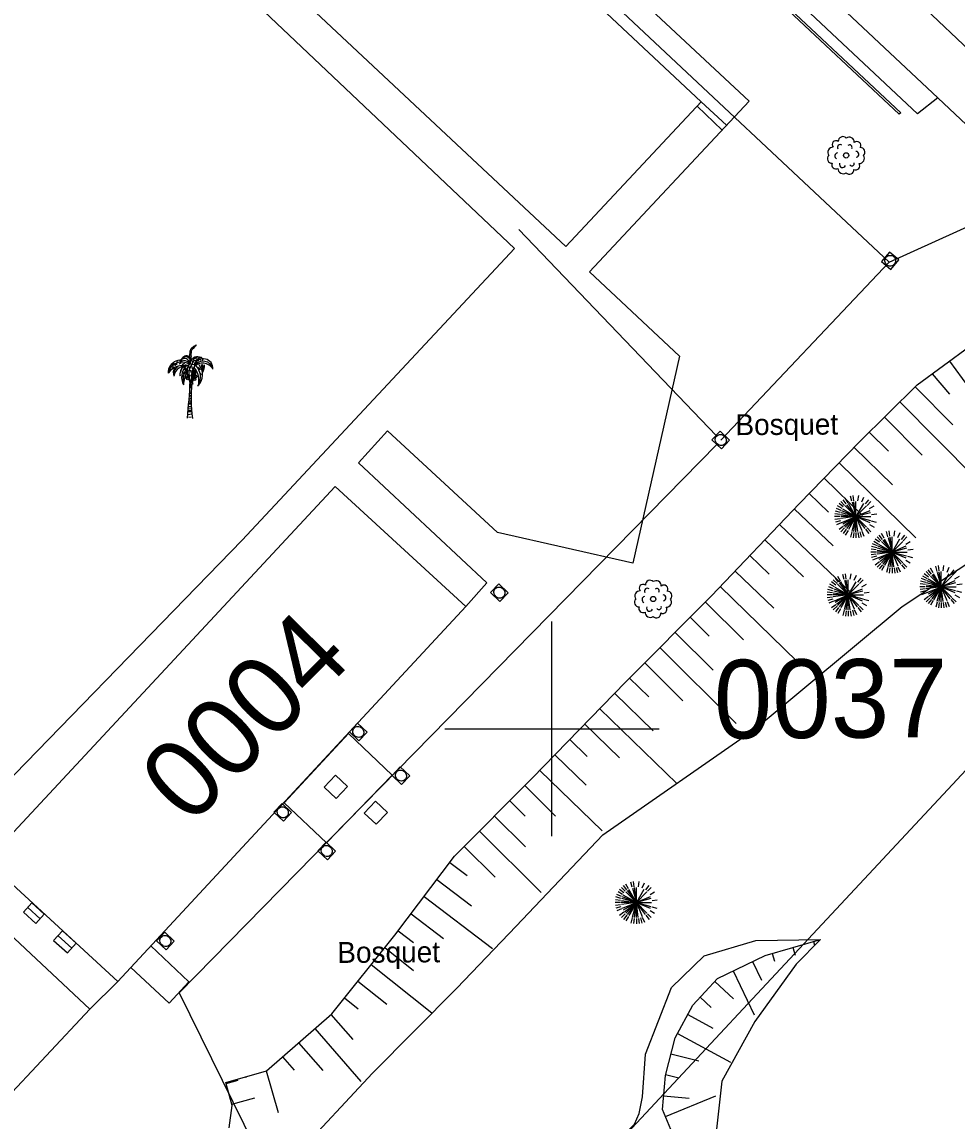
# Model space of a CAD drawing. Extents: x 343997 to 344255, y 298512 to 298767.
# Drawn here: x 344175.3 to 344218.9, y 298581.7 to 298632.9 of the extents above; entities that cross this region are included whole.
import ezdxf

# ---------------------------------------------------------------- set-up
doc = ezdxf.new("R2010")
doc.units = 0
for name, color, linetype in [('Default', 7, 'Continuous'), ('DH_CADRE -CARTOUCHE', 7, 'Continuous'), ('DH_CADRE-CARTOUCHE', 7, 'Continuous'), ('DH_CADRE-CARTOUCHE-NORD', 7, 'Continuous'), ('DH_TEXTE', 7, 'Continuous'), ('DIR-Projet VRD1', 7, 'Continuous'), ('GO_DALLE', 7, 'Continuous'), ('GO_ESCALIER', 7, 'Continuous'), ('GO_MUR', 7, 'Continuous'), ('PC_REBAR', 7, 'Continuous'), ('PS_HATCH', 7, 'Continuous'), ('PS_OBJECT', 7, 'Continuous'), ('PS_PLATE', 7, 'Continuous'), ('RES_EAU PLUVIALE', 7, 'Continuous')]:
    doc.layers.add(name, color=color, linetype=linetype)

# ---------------------------------------------------------------- blocks, each defined once
blk = doc.blocks.new('REG_INC')
at = {"layer": 'Default'}
for p, q in [((0, 0.1), (0.1, 0.1)), ((0, 0), (0, 0.1)), ((0.1, 0.1), (0.1, 0)), ((0.1, 0), (0, 0))]:
    blk.add_line(p, q, dxfattribs=at)
for centre, start, end in [((0.05, 0.0498), 90.00577, 135.00577), ((0.05, 0.05), 45.00687, 90.00687), ((0.0498, 0.05), 135.00554, 180.00554), ((0.0501, 0.05), 180.00663, 225.00663), ((0.0499, 0.0498), 225.00686, 270.00686), ((0.0499, 0.05), 270.00577, 315.00577), ((0.0499, 0.0499), 0.00663, 45.00663), ((0.0501, 0.0499), 315.00554, 0.00554)]:
    blk.add_arc(centre, 0.044, start, end, dxfattribs=at)
blk = doc.blocks.new('R3')
at = {"layer": 'Default'}
for p, q in [((0, 0.1), (0.1, 0.1)), ((0, 0), (0, 0.1)), ((0.1, 0.1), (0.1, 0)), ((0.1, 0), (0, 0))]:
    blk.add_line(p, q, dxfattribs=at)
blk = doc.blocks.new('COCO')
at = {"layer": 'Default'}
for p, q in [((-0.0037, 0.106), (0.0056, 0.1071)), ((0.0058, 0.114), (-0.003, 0.1162)), ((-0.0026, 0.1226), (0.0061, 0.1212)), ((-0.0062, 0.0537), (0.0046, 0.0552)), ((0.0047, 0.0655), (-0.0058, 0.0642)), ((-0.0046, 0.0891), (0.0052, 0.0927)), ((0.0054, 0.0998), (-0.0041, 0.0985)), ((0.0046, 0.0033), (-0.0076, 0.0051)), ((-0.0073, 0.017), (0.0045, 0.0209)), ((0.0045, 0.0292), (-0.007, 0.0288)), ((-0.0068, 0.0371), (0.0045, 0.0374)), ((0.0045, 0.047), (-0.0065, 0.0453))]:
    blk.add_line(p, q, dxfattribs=at)
for points in [[(0.0029, 0.2551), (-0.0016, 0.2896), (0.0002, 0.3125), (0.0059, 0.3241), (0.0173, 0.3348), (0.0189, 0.3356), (0.0282, 0.3415), (0.0266, 0.3373), (0.02, 0.3318), (0.0143, 0.3247), (0.0093, 0.32), (0.0081, 0.3165), (0.0057, 0.3133), (0.0057, 0.3099), (0.006, 0.3037), (0.0039, 0.2989), (0.0039, 0.2944), (0.0049, 0.2877), (0.0037, 0.2841), (0.0013, 0.2736)], [(-0.0636, 0.2639), (-0.0541, 0.2608)], [(-0.0421, 0.258), (-0.0503, 0.2523)], [(-0.0487, 0.268), (-0.0386, 0.265)], [(0.0013, 0.2736), (0.0036, 0.2813), (0.0046, 0.2746)], [(0.0133, 0.2608), (0.0185, 0.2634)], [(0.0196, 0.2687), (0.0323, 0.2715)], [(0.0283, 0.2765), (0.0331, 0.2786)], [(-0.0746, 0.2559), (-0.0864, 0.2483)], [(-0.077, 0.2413), (-0.0836, 0.2333)], [(-0.0607, 0.2534), (-0.0704, 0.2443)], [(-0.0183, 0.2493), (-0.0348, 0.2417), (-0.0401, 0.2307), (-0.0448, 0.2203), (-0.0471, 0.2086), (-0.0474, 0.2023), (-0.0466, 0.1973), (-0.0455, 0.2054), (-0.0451, 0.2146), (-0.0387, 0.2292), (-0.0351, 0.2354), (-0.0284, 0.2404), (-0.0233, 0.2445), (-0.0012, 0.2495)], [(-0.0256, 0.2553), (-0.0385, 0.2508)], [(-0.0276, 0.2151), (-0.0329, 0.2086)], [(-0.0203, 0.2314), (-0.0274, 0.2258)], [(-0.023, 0.2152), (-0.0237, 0.2043)], [(-0.0161, 0.2218), (-0.0158, 0.2122)], [(-0.004, 0.2247), (-0.0081, 0.2179)], [(0.0015, 0.2414), (-0.0056, 0.2352)], [(0.0022, 0.224), (0.0043, 0.213)], [(0.0081, 0.2404), (0.0106, 0.2299)], [(0.0385, 0.237), (0.0469, 0.2254)], [(0.0473, 0.2115), (0.0509, 0.2012)], [(-0.0321, 0.1997), (-0.0364, 0.19)], [(-0.0059, 0.2024), (-0.0083, 0.1998)], [(-0.0025, 0.2032), (0.0002, 0.1954)], [(-0.0055, 0.0716), (0.0048, 0.0717), (0.0049, 0.0787), (-0.0051, 0.0795)]]:
    blk.add_lwpolyline(points, dxfattribs=at)
for centre, radius in [((-0.0187, 0.1897), 0.00384), ((-0.0144, 0.1978), 0.00616), ((-0.0124, 0.1896), 0.00376), ((-0.011, 0.184), 0.00471), ((0.0134, 0.1862), 0.00549), ((0.0208, 0.1822), 0.00626), ((0.0254, 0.1938), 0.00628)]:
    blk.add_circle(centre, radius, dxfattribs=at)
for centre, radius, start, end in [((-0.0427, 0.2113), 0.0595, 43.6121, 181.4625), ((-0.038, 0.1964), 0.0648, 57.9192, 166.6201), ((-0.0123, 0.259), 0.0323, 122.3475, 158.7636), ((-0.0199, 0.2618), 0.0238, 4.5218, 154.101), ((-0.0252, 0.2556), 0.0231, 4.2441, 134.2103), ((-0.016, 0.2647), 0.0255, 21.0861, 122.3475), ((0.0376, 0.2508), 0.0372, 113.7681, 175.3309), ((0.0376, 0.2508), 0.0372, 113.7681, 175.3309), ((0.0418, 0.2527), 0.0326, 97.1248, 183.9512), ((0.1025, 0.2053), 0.0958, 126.6858, 153.1664), ((0.059, 0.2015), 0.0548, 29.5654, 139.3517), ((0.0618, 0.2316), 0.0451, 356.1627, 159.0009), ((0.0609, 0.2187), 0.0468, 12.1077, 148.3146), ((0.0344, 0.2407), 0.0451, 69.0817, 104.862), ((-0.0157, 0.2027), 0.074, 51.2475, 54.5217), ((-0.1005, 0.1577), 0.1786, 37.5668, 40.5156), ((-0.0254, 0.228), 0.0869, 28.4725, 37.0965), ((0.0493, 0.2767), 0.00679, 35.3205, 126.6858), ((-0.0054, 0.2379), 0.0738, 25.8194, 35.3205), ((-0.0291, 0.1543), 0.0918, 76.7389, 142.8025), ((-0.03, 0.212), 0.0482, 151.1331, 199.5942), ((-0.0196, 0.1874), 0.0565, 78.514, 171.3504), ((-0.032, 0.2055), 0.0433, 119.0834, 188.7621), ((0.0362, 0.1922), 0.0754, 136.7113, 208.8221), ((0.0551, 0.179), 0.0879, 137.733, 194.3716), ((0.0649, 0.1599), 0.0949, 145.5146, 182.4528), ((0.062, 0.2159), 0.0753, 153.0868, 230.1124), ((0.0659, 0.2068), 0.0718, 142.3554, 222.2794), ((-0.0007, 0.2465), 0.00563, 81.7475, 144.3035), ((-0.0189, 0.121), 0.1324, 71.3715, 81.7475), ((0.0294, 0.2595), 0.0256, 198.6765, 199.7627), ((0.0963, 0.1939), 0.09, 143.9866, 203.4288), ((0.0544, 0.1816), 0.0474, 137.1953, 172.8987), ((0.0308, 0.2014), 0.0226, 121.4297, 182.29), ((2.7302, 0.0106), 2.7266, 175.4791, 176.5597), ((0.0311, 0.2152), 0.0219, 141.856, 191.5175), ((0.0242, 0.1964), 0.0147, 110.9727, 165.9756), ((0.0404, 0.1878), 0.0354, 125.0585, 146.3893), ((0.0398, 0.2098), 0.0301, 136.4569, 162.0685), ((0.0357, 0.2084), 0.0244, 133.1184, 172.7534), ((-0.0759, 0.1958), 0.0922, 344.8505, 15.8988), ((-0.0404, 0.2045), 0.0619, 329.4666, 26.6793), ((-0.0289, 0.211), 0.0564, 317.8279, 12.3386), ((-0.0543, 0.1744), 0.096, 344.8781, 41.1461), ((-0.0341, 0.19), 0.0828, 46.9767, 50.1231), ((-0.0341, 0.19), 0.0828, 334.0687, 41.194), ((-0.0157, 0.2027), 0.074, 315.1472, 39.0239), ((-0.1704, 0.1849), 0.2327, 7.5978, 16.3666), ((-0.0254, 0.228), 0.0869, 350.8883, 14.7063), ((-0.0482, 0.2552), 0.1161, 339.3597, 356.5925), ((-8.5428, 0.7294), 8.5622, 355.11326, 356.26352), ((-0.0279, 0.1637), 0.0281, 2.1499, 36.6325), ((-0.0265, 0.1505), 0.0316, 339.9997, 25.7228), ((0.0199, 0.166), 0.0176, 166.9443, 185.5966), ((0.0372, 0.1847), 0.0277, 133.5956, 173.487), ((0.0808, 0.1542), 0.0777, 142.2358, 156.28)]:
    blk.add_arc(centre, radius, start, end, dxfattribs=at)
blk.add_ellipse((2.7425, 0.0272), major_axis=(-2.7371, 0.0966), ratio=0.529859, start_param=6.255729, end_param=6.369141, dxfattribs=at)
blk = doc.blocks.new('ARB1')
at = {"layer": 'Default'}
blk.add_circle((0, 0), 0.0122, dxfattribs=at)
for centre, radius, start, end in [((-0.0471, 0.0503), 0.0183, 53.9554, 222.2066), ((-0.0153, 0.0664), 0.0211, 43.6925, 183.5969), ((0.0139, 0.0613), 0.0241, 358.4583, 125.1928), ((0.0501, 0.0468), 0.0183, 325.1444, 131.0175), ((-0.0613, 0.0139), 0.0241, 88.4583, 215.1928), ((-0.0373, -0.0024), 0.0149, 103.7092, 242.3465), ((-0.0276, 0.037), 0.0134, 52.4396, 209.5496), ((0.0164, 0.038), 0.0112, 330.5895, 133.7127), ((0.0458, 0.0052), 0.0137, 276.6214, 88.967), ((0.0613, -0.0139), 0.0241, 268.4583, 35.1928), ((0.0664, 0.0153), 0.0211, 313.6925, 93.5969), ((-0.0664, -0.0153), 0.0211, 133.6925, 273.5969), ((-0.0478, -0.0443), 0.019, 155.2243, 300.9377), ((-0.0163, -0.042), 0.0148, 159.5371, 338.1663), ((0.0271, -0.038), 0.0112, 210.5895, 13.7127), ((0.0448, -0.0483), 0.0188, 243.1323, 33.0297), ((-0.0139, -0.0613), 0.0241, 178.4583, 305.1928), ((0.0153, -0.0664), 0.0211, 223.6925, 3.5969)]:
    blk.add_arc(centre, radius, start, end, dxfattribs=at)
blk = doc.blocks.new('ARB2')
at = {"layer": 'Default'}
for p, q in [((-0.0575, 0.0453), (-0.0775, 0.0605)), ((-0.0513, 0.0525), (-0.0688, 0.0702)), ((-0.0438, 0.0589), (-0.0588, 0.0786)), ((-0.0356, 0.0642), (-0.0481, 0.0858)), ((-0.0181, 0.0716), (-0.0244, 0.0956)), ((-0.0088, 0.0736), (-0.0119, 0.0983)), ((0.0106, 0.0736), (0.0144, 0.0983)), ((0.0287, 0.0684), (0.0388, 0.0914)), ((0.0456, 0.0589), (0.0612, 0.0786)), ((0.0531, 0.0525), (0.0706, 0.0702)), ((-0.0731, 0), (-0.0981, 0)), ((-0.0725, 0.01), (-0.0969, 0.0133)), ((-0.0706, 0.0195), (-0.0944, 0.0259)), ((-0.0675, 0.0286), (-0.09, 0.0381)), ((-0.0631, 0.0373), (-0.0844, 0.0497)), ((0.065, 0.0373), (0.0862, 0.0497)), ((0.0744, 0.01), (0.0987, 0.0133)), ((-0.0725, -0.01), (-0.0969, -0.0133)), ((-0.0706, -0.0195), (-0.0944, -0.0259)), ((-0.0675, -0.0287), (-0.09, -0.0383)), ((-0.0575, -0.0455), (-0.0775, -0.0605)), ((0.065, -0.0373), (0.0862, -0.0498)), ((0.0725, -0.0195), (0.0963, -0.0259)), ((-0.0513, -0.0527), (-0.0688, -0.0702)), ((-0.0438, -0.0591), (-0.0588, -0.0787)), ((-0.0356, -0.0644), (-0.0481, -0.0859)), ((-0.0181, -0.0717), (-0.0244, -0.0956)), ((-0.0088, -0.0737), (-0.0119, -0.0983)), ((0.0013, -0.0741), (0.0013, -0.0989)), ((0.0106, -0.0737), (0.0144, -0.0983)), ((0.02, -0.0717), (0.0263, -0.0956)), ((0.0287, -0.0686), (0.0388, -0.0916)), ((0.0456, -0.0591), (0.0612, -0.0787)), ((0.0531, -0.0527), (0.0706, -0.0702))]:
    blk.add_line(p, q, dxfattribs=at)
for points in [[(-0.0688, 0.0091), (0.0013, 0), (-0.0338, 0.0608)], [(-0.0419, 0.0556), (0.0013, 0), (-0.0638, 0.0269)], [(-0.0169, 0.0677), (0.0013, 0), (-0.06, 0.035)], [(0.0013, 0.0008), (0.0013, 0), (-0.0081, 0.0695)], [(0.0362, 0.0608), (0.0013, 0), (0.0013, 0.0702)], [(-0.0487, -0.0497), (0.0013, 0), (-0.0694, 0)], [(-0.0638, -0.0269), (0.0013, 0), (-0.0688, -0.0092)], [(-0.0487, 0.0495), (0.0013, 0), (-0.0669, 0.0181)], [(-0.0169, -0.0678), (0.0013, 0), (-0.06, -0.0352)], [(-0.0544, -0.0428), (0.0013, 0), (-0.0338, -0.0608)], [(-0.0081, -0.0695), (0.0013, 0), (-0.0419, -0.0558)], [(0.0013, -0.0702), (0.0013, 0), (0, 0)], [(0.0656, 0.0269), (0.0013, 0), (0.0506, 0.0495)], [(0.0688, 0.0181), (0.0013, 0), (0.0713, 0)], [(0.0438, -0.0558), (0.0013, 0), (0.0656, -0.0269)], [(0.0506, -0.0497), (0.0013, 0), (0.0688, -0.0181)], [(0.01, -0.0695), (0.0013, 0), (0.0281, -0.0648)], [(0.0019, 0), (0.0013, 0), (0.0013, -0.0009)]]:
    blk.add_lwpolyline(points, dxfattribs=at)

msp = doc.modelspace()

# ---------------------------------------------------------------- linework, layer by layer
at = {"layer": 'DH_CADRE -CARTOUCHE'}
for p, q in [((344200, 298595), (344200, 298605)), ((344195, 298600), (344205, 298600))]:
    msp.add_line(p, q, dxfattribs=at)
msp.add_lwpolyline([(343997.309, 298660.673), (344147.183, 298520.807), (344245.09, 298625.72), (344095.215, 298765.586)], close=True, dxfattribs=at)
at = {"layer": 'DH_CADRE-CARTOUCHE'}
msp.add_lwpolyline([(344173.884, 298668.877), (344175.641, 298668.318), (344176.928, 298667.79), (344178.107, 298666.872), (344194.798, 298651.17), (344217.989, 298629.411), (344240.944, 298607.781), (344244.256, 298604.654)], dxfattribs=at)
at = {"layer": 'DH_CADRE-CARTOUCHE-NORD'}
for p, q in [((344193.828, 298642.286), (344215.714, 298621.751)), ((344215.714, 298621.751), (344222.758, 298624.96)), ((344198.454, 298623.276), (344207.649, 298613.67)), ((344215.714, 298621.751), (344207.87, 298613.462)), ((344207.679, 298613.259), (344182.63, 298587.693)), ((344182.63, 298587.693), (344198.438, 298555.558))]:
    msp.add_line(p, q, dxfattribs=at)
at = {"layer": 'DIR-Projet VRD1'}
msp.add_line((344180.02, 298669.219), (344245.896, 298606.412), dxfattribs=at)
at = {"layer": 'GO_DALLE'}
for points in [[(344173.637, 298593.851), (344172.292, 298595.161), (344185.567, 298608.8), (344198.259, 298622.397), (344163.217, 298655.561), (344163.898, 298656.291), (344171.693, 298664.218), (344209.192, 298629.258), (344201.744, 298621.299), (344205.95, 298617.379), (344203.771, 298607.721), (344197.46, 298609.156), (344192.341, 298613.899), (344190.988, 298612.393), (344196.963, 298606.8), (344195.985, 298605.701)], [(344208.14, 298628.134), (344206.962, 298629.231), (344206.772, 298629.027), (344207.928, 298627.907)], [(344173.444, 298593.641), (344172.427, 298592.568), (344178.462, 298586.939), (344174.396, 298582.587), (344168.376, 298588.228), (344167.085, 298586.853), (344168.386, 298585.586), (344159.324, 298576.069), (344121.411, 298611.054), (344130.716, 298620.945), (344149.461, 298603.379), (344147.717, 298601.519)], [(344179.76, 298588.225), (344178.462, 298586.939), (344172.427, 298592.568), (344173.444, 298593.641), (344173.637, 298593.851)], [(344181.304, 298589.888), (344183.07, 298588.205), (344182.156, 298587.216), (344180.365, 298588.877)]]:
    msp.add_lwpolyline(points, dxfattribs=at)
msp.add_lwpolyline([(344187.514, 298596.559), (344189.49, 298594.691), (344192.553, 298597.847), (344190.509, 298599.787)], close=True, dxfattribs=at)
at = {"layer": 'GO_ESCALIER'}
for points in [[(344175.763, 298591.898), (344175.363, 298591.462), (344175.943, 298590.936), (344176.339, 298591.368)], [(344177.19, 298590.587), (344176.772, 298590.132), (344177.42, 298589.564), (344177.824, 298590.004)]]:
    msp.add_lwpolyline(points, close=True, dxfattribs=at)
for points in [[(344176.141, 298591.152), (344175.563, 298591.68)], [(344177.622, 298589.784), (344176.981, 298590.359)]]:
    msp.add_lwpolyline(points, dxfattribs=at)
at = {"layer": 'GO_MUR'}
for points in [[(344162.931, 298666.015), (344158.413, 298661.325), (344158.342, 298661.39), (344163.216, 298666.766), (344163.731, 298667.308), (344164.688, 298668.072), (344165.676, 298668.545), (344166.447, 298668.825), (344167.222, 298669.059), (344168.509, 298669.289), (344169.751, 298669.392), (344170.251, 298669.414), (344170.803, 298669.375), (344172.06, 298669.227), (344173.884, 298668.877), (344175.641, 298668.318), (344176.928, 298667.79), (344178.107, 298666.872), (344194.798, 298651.17), (344217.989, 298629.411), (344217.037, 298628.671)], [(344217.037, 298628.671), (344194.049, 298650.256), (344176.274, 298666.89)], [(344175.978, 298666.428), (344193.686, 298649.877), (344216.254, 298628.72), (344216.185, 298628.648), (344193.618, 298649.804), (344175.917, 298666.349)]]:
    msp.add_lwpolyline(points, dxfattribs=at)
at = {"layer": 'PS_HATCH'}
msp.add_lwpolyline([(344182.365, 298573.436), (344182.886, 298573.416), (344183.782, 298573.006), (344188.242, 298571.307), (344188.925, 298571.234), (344191.696, 298571.482), (344193.065, 298571.873), (344193.915, 298572.359), (344194.821, 298573.435), (344196.721, 298576.256), (344197.328, 298576.829), (344198.067, 298577.284), (344202.461, 298580.187), (344203.841, 298581.577), (344204.07, 298582.072), (344204.22, 298582.851), (344204.366, 298584.836), (344205.57, 298587.951), (344207.101, 298589.427), (344209.508, 298590.137), (344212.523, 298590.19)], dxfattribs=at)
at = {"layer": 'PS_OBJECT'}
for p, q in [((344218.523, 298617.14), (344220.003, 298615.124)), ((344217.717, 298616.549), (344218.529, 298615.598)), ((344216.924, 298615.941), (344218.685, 298614.164)), ((344216.214, 298615.237), (344219.734, 298611.684)), ((344215.503, 298614.533), (344217.263, 298612.756)), ((344214.793, 298613.828), (344215.68, 298612.948)), ((344214.086, 298613.12), (344215.876, 298611.374)), ((344213.388, 298612.404), (344216.967, 298608.912)), ((344212.689, 298611.689), (344214.479, 298609.942)), ((344211.99, 298610.973), (344212.891, 298610.105)), ((344211.295, 298610.254), (344213.106, 298608.53)), ((344210.605, 298609.53), (344214.228, 298606.081)), ((344209.915, 298608.805), (344211.727, 298607.081)), ((344209.226, 298608.081), (344210.131, 298607.218)), ((344208.536, 298607.356), (344210.347, 298605.632)), ((344207.846, 298606.631), (344211.43, 298603.143)), ((344207.15, 298605.913), (344208.923, 298604.149)), ((344206.445, 298605.204), (344207.331, 298604.322)), ((344205.739, 298604.495), (344207.512, 298602.731)), ((344205.034, 298603.786), (344208.579, 298600.258)), ((344204.328, 298603.077), (344206.1, 298601.313)), ((344203.622, 298602.368), (344204.514, 298601.492)), ((344202.923, 298601.653), (344204.716, 298599.91)), ((344202.226, 298600.936), (344205.813, 298597.45)), ((344201.529, 298600.218), (344203.143, 298598.65)), ((344200.832, 298599.501), (344201.639, 298598.717)), ((344200.135, 298598.784), (344201.587, 298597.372)), ((344199.438, 298598.066), (344202.343, 298595.243)), ((344198.736, 298597.353), (344200.172, 298595.925)), ((344198.031, 298596.644), (344198.749, 298595.93)), ((344197.325, 298595.935), (344198.761, 298594.506)), ((344196.62, 298595.225), (344199.492, 298592.369)), ((344195.915, 298594.516), (344197.351, 298593.088)), ((344195.246, 298593.775), (344196.053, 298593.163)), ((344194.641, 298592.978), (344196.255, 298591.754)), ((344194.036, 298592.182), (344197.23, 298589.758)), ((344193.432, 298591.385), (344194.948, 298590.234)), ((344192.827, 298590.588), (344193.547, 298590.042)), ((344192.207, 298589.803), (344193.547, 298588.73)), ((344211.229, 298589.814), (344211.333, 298589.455)), ((344212.189, 298590.093), (344212.239, 298589.92)), ((344209.347, 298589.153), (344209.766, 298588.282)), ((344210.268, 298589.535), (344210.372, 298589.178)), ((344191.581, 298589.023), (344194.408, 298586.757)), ((344208.446, 298588.719), (344209.43, 298586.677)), ((344190.956, 298588.242), (344192.298, 298587.166)), ((344207.586, 298588.229), (344208.468, 298587.421)), ((344190.33, 298587.462), (344190.967, 298586.951)), ((344206.911, 298587.491), (344207.428, 298587.017)), ((344189.698, 298586.687), (344190.718, 298585.518)), ((344206.332, 298586.684), (344207.5, 298586.046)), ((344188.945, 298586.029), (344191.098, 298583.562)), ((344205.852, 298585.806), (344208.318, 298584.459)), ((344188.191, 298585.372), (344189.327, 298584.07)), ((344187.437, 298584.714), (344187.977, 298584.096)), ((344205.548, 298584.859), (344206.84, 298584.527)), ((344186.682, 298584.06), (344187.246, 298582.115)), ((344184.813, 298583.473), (344185.367, 298583.624)), ((344185.721, 298583.781), (344185.731, 298583.748)), ((344205.299, 298583.89), (344205.913, 298583.733)), ((344185.076, 298582.508), (344186.155, 298582.803)), ((344205.205, 298582.895), (344206.403, 298582.792)), ((344205.289, 298581.925), (344207.633, 298582.9))]:
    msp.add_line(p, q, dxfattribs=at)
for points in [[(344184.947, 298581.398), (344185.091, 298582.452), (344184.802, 298583.514), (344186.691, 298584.063), (344189.735, 298586.719), (344192.676, 298590.389), (344195.465, 298594.065), (344199.099, 298597.718), (344203.435, 298602.18), (344207.43, 298606.195), (344211.519, 298610.49), (344214.324, 298613.364), (344217.026, 298616.042), (344219.477, 298617.84), (344221.365, 298618.23), (344223.701, 298617.841), (344226.31, 298616.105), (344230.086, 298613.088), (344233.778, 298609.542), (344238.683, 298603.912), (344241.181, 298601.359)], [(344163.934, 298561.868), (344170.201, 298566.564), (344176.522, 298569.299), (344180.879, 298572.338), (344183.313, 298574.136), (344185.048, 298576.477), (344188.051, 298580.099), (344191.638, 298583.956), (344195.571, 298587.909), (344198.338, 298590.807), (344202.379, 298595.055), (344209.468, 298599.999), (344216.32, 298605.698), (344221.544, 298609.146), (344226.03, 298610.067), (344230.196, 298608.376), (344234.376, 298605.349), (344238.337, 298601.801), (344240.148, 298600.253)], [(344212.606, 298570.74), (344212.3, 298571.239), (344209.819, 298574.721), (344207.66, 298577.896), (344205.926, 298580.392), (344205.15, 298582.259), (344205.287, 298583.842), (344205.737, 298585.596), (344206.567, 298587.115), (344207.71, 298588.364), (344209.939, 298589.439), (344212.523, 298590.19)], [(344212.523, 298590.19), (344211.38, 298589.036), (344209.463, 298586.355), (344207.924, 298583.579), (344207.66, 298581.209), (344209.646, 298577.609), (344212.346, 298573.48), (344213.514, 298571.713)]]:
    msp.add_lwpolyline(points, dxfattribs=at)
at = {"layer": 'PS_PLATE'}
for points in [[(344200.65, 298622.487), (344165.426, 298655.454), (344171.721, 298662.233), (344206.962, 298629.231)], [(344173.637, 298593.851), (344189.896, 298611.294), (344195.985, 298605.701), (344179.76, 298588.225)]]:
    msp.add_lwpolyline(points, close=True, dxfattribs=at)

# ---------------------------------------------------------------- block references
at = {"layer": 'DH_CADRE-CARTOUCHE-NORD', "xscale": 7.66204299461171, "yscale": 7.6091287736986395, "rotation": -133.69158000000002}
for p in [(344189.916, 298597.839), (344191.781, 298596.632)]:
    msp.add_blockref('R3', p, dxfattribs=at)
at = {"layer": 'PC_REBAR', "xscale": 10, "yscale": 10}
for name, p in [('ARB1', (344213.711, 298626.73)), ('COCO', (344183.131, 298614.483)), ('ARB2', (344214.155, 298609.894)), ('ARB2', (344215.842, 298608.242)), ('ARB2', (344218.129, 298606.626)), ('ARB2', (344213.801, 298606.244)), ('ARB1', (344204.718, 298606.052)), ('ARB2', (344203.924, 298591.906))]:
    msp.add_blockref(name, p, dxfattribs=at)
at = {"layer": 'RES_EAU PLUVIALE'}
for p, xscale, yscale, rotation in [((344215.364, 298621.784), 5.69802741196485, -5.70461169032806, 50.268059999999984), ((344207.841, 298613.874), 6.07622101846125, -5.58454252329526, -43.338150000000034), ((344197.519, 298606.76), 6.07622101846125, -5.58454252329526, -43.338150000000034), ((344190.944, 298600.269), 6.07622101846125, -5.58454252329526, -43.338150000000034), ((344192.932, 298598.234), 6.07622101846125, -5.58454252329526, -43.338150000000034), ((344187.425, 298596.522), 6.07622101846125, -5.58454252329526, -43.338150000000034), ((344189.473, 298594.718), 6.07622101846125, -5.58454252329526, -43.338150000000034), ((344181.953, 298590.522), 6.07622101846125, -5.58454252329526, -43.338150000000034)]:
    msp.add_blockref('REG_INC', p, dxfattribs=dict(at, xscale=xscale, yscale=yscale, rotation=rotation))

# ---------------------------------------------------------------- texts
at = {"layer": 'DH_TEXTE'}
for s, height, rotation, p in [('Bosquet', 0.9758, 0.3665, (344208.554, 298613.689)), ('0004', 3.662, 45.3665, (344183.129, 298595.424)), ('0037', 3.662, 0.3665, (344207.556, 298599.547)), ('Bosquet', 0.9758, 0.3665, (344189.996, 298589.09))]:
    msp.add_text(s, height=height, rotation=rotation, dxfattribs=at).set_placement(p)

doc.saveas('drawing.dxf')
